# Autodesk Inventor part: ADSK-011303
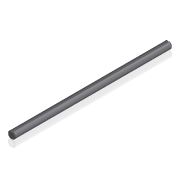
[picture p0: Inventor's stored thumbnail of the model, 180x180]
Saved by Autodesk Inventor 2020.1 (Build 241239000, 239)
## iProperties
Created: 1999-11
Part Number: ADSK-011303
Material: Acier (alliage faible hypertrempé)
Description: SHFT1K,RG,EX,06,140,SHAFT,MNT,FINGER
Document SubType Name: Modeling
Designer: sspink
Density: 7.84 g/cm^3
Appearance: Metal-Steel(Polish)
Mass: 526.307 g
Surface Area: 196.253 cm^2
Volume: 67.131 cm^3
Control State: 0
Checked Out: False
Last Check In By: sspink
Last Check In Date: 1999-12-16
Master: False
Shininess: 0.0
Length Units: 11269
Angle Units: 11279
Time Units: 11290
Mass Units: 11283
Length Display Precision: 3
Angle Display Precision: 2
Compacted: True
Material Desc: ROUND,DGP,0.625 DIA
Cutlength: 14
Material_number: A089692
Dimensions: 16x15,6x355 mm
Mass: 0,526 kg
DocNumber: ADSK-011303.ipt
Folder: 01 - Themengebiete\Simplification\01 - Packaging machine\
VDS_Category: 3D Komponenten
Density: 0.0
Volumn: 0.0
Area: 0.0
PropertySet Name: Model Information
Author: sspink
Revision Number: -
Title: SHFT1K,RG,EX,06,140,SHAFT,MNT,FINGER
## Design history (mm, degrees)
node "Solide1"
  node "Extrusion1" dims "d1" = 355, "d2" = 0
sketch "Sketch1"
  geometry: L1 (-2.5, 8)-(2.5, 8); L2 (2.5, 8)-(2.5, 5.5); L3 (2.5, 5.5)-(-2.5, 5.5); L4 (-2.5, 5.5)-(-2.5, 8); A1 r 8 centre (0, 0) between (-2.5, 7.599) and (2.5, 7.599); 1 further point
  constraints: 8 end point, 2 parallel, 2 point on circle, 2 point on line, 1 centre point, 1 coincident, 1 horizontal, 1 perpendicular
  dimensions: "d0" = 16 diameter of A1; "d9" = 5 distance between parallel lines of L2 L4; "d10" = 2.5 distance of L3.end L1.start (= 0.5 x d9); "d11" = 8 distance from line of A1.centre L1 (= 0.5 x d0); "d12" = 2.5 distance from line of A1.centre L4 (= 0.5 x d9)
chamfer "Fase1" distance "d13" = 1; stored, may be unused: second distance "d14" = 2, angle "d15" = 45 deg
node "Corps solides"
node "Corps surfaciques"
